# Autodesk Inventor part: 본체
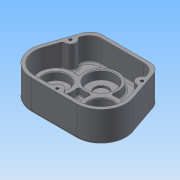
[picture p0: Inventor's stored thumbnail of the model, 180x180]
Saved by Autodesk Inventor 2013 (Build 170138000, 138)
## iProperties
Created: 2014-12
Part Number: 본체
Material: 일반
Document SubType Name: Modeling
Designer: Administrator
Density: 1 g/cm^3
Author: Administrator
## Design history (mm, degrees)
sketch "스케치1"
  geometry: L1 (0, 0)-(-32.527, -32.527); L2 (0, 0)-(32.527, -32.527); L3 (0, 0)-(0, -46); L4 (-47, 36)-(47, 36); L5 (-32.527, -68.527)-(32.527, -68.527); L6 (47, 36)-(66.565, -20.803); L7 (-47, 36)-(-66.565, -20.803); A1 r 46 centre (0, 0) between (-32.527, -32.527) and (32.527, -32.527); A2 r 36 centre (32.527, -32.527) between (32.527, -68.527) and (66.565, -20.803); A3 r 36 centre (-32.527, -32.527) between (-66.565, -20.803) and (-32.527, -68.527); 2 further points
  constraints: 14 end point, 7 point on circle, 3 centre point, 3 coincident, 3 tangent, 1 midpoint, 1 parallel, 1 perpendicular, 1 vertical, 1 vertical alignment
  dimensions: "d2" = 92 diameter of A1; "d3" = 90 deg angle of L2 L1; "d5" = 45 deg angle of L3 L1; "d9" = 94 distance of L4.start L4.end; "d10" = 36 distance from line of L4 point (0, 0)
extrude "돌출1" new body sketch "스케치1" distance "d11" = 44; taper "d12" = 0 deg
fillet "모깎기1" dims "d13" = 18
fillet "모깎기3" dims "d15" = 3
sketch "스케치27"
  geometry: L1 (-66.565, -20.803)-(-51.181, 23.862) reference; L2 (51.181, 23.862)-(66.565, -20.803) reference; L3 (-34.162, 36)-(34.162, 36) reference; L4 (-43.434, 31)-(-61.837, -22.432); L5 (43.434, 31)-(61.837, -22.432); L6 (-32.527, -63.527)-(32.527, -63.527); L7 (-43.434, 31)-(43.434, 31); L8 (-34.162, 36)-(34.162, 36) reference; L9 (51.181, 23.862)-(66.565, -20.803) reference; L10 (32.527, -68.527)-(-32.527, -68.527) reference; L11 (-66.565, -20.803)-(-51.181, 23.862) reference; A1 r 36 centre (-32.527, -32.527) between (-66.565, -20.803) and (-32.527, -68.527) reference; A2 r 36 centre (32.527, -32.527) between (32.527, -68.527) and (66.565, -20.803) reference; A3 r 31 centre (32.527, -32.527) between (32.527, -63.527) and (61.837, -22.432); A4 r 31 centre (-32.527, -32.527) between (-61.837, -22.432) and (-32.527, -63.527); A5 r 18 centre (-34.162, 18) between (-34.162, 36) and (-51.181, 23.862) reference; A6 r 18 centre (34.162, 18) between (51.181, 23.862) and (34.162, 36) reference; A7 r 36 centre (32.527, -32.527) between (32.527, -68.527) and (66.565, -20.803) reference; A8 r 36 centre (-32.527, -32.527) between (-66.565, -20.803) and (-32.527, -68.527) reference; 3 further points
  constraints: 8 end point, 4 point on circle, 4 tangent, 3 coincident, 2 centre point, 2 parallel, 1 midpoint, 1 vertical alignment
  dimensions: "d88" = 62 diameter of A3; "d90" = 62 diameter of A4; "d93" = 5 distance from line of L1 L4.start; "d94" = 5 distance from line of L3 point (0, 31); "d95" = 43.43386 distance of L5.start point (0, 31)
extrude "돌출17" cut sketch "스케치27" distance "d96" = 34; taper "d97" = 0 deg
fillet "모깎기5" dims "d98" = 18
sketch "스케치35"
  geometry: L1 (-61.837, -22.432)-(-47.615, 18.862) reference; L2 (-34.162, 36)-(34.162, 36) reference; A1 r 8 centre (-51.7, 7) between (-54.305, -0.564) and (-49.095, 14.564); 1 further point
  constraints: 3 point on line, 2 point on circle, 1 centre point
  dimensions: "d114" = 16 diameter of A1; "d115" = 29 distance from line of L2 A1.centre
extrude "돌출23" join sketch "스케치35" stored distance "d116" = 3; taper "d117" = 0 deg
sketch "스케치36"
  geometry: L1 (32.527, -63.527)-(-32.527, -63.527) reference; A1 r 8 centre (0, -63.527) between (8, -63.527) and (-8, -63.527); 1 further point
  constraints: 2 point on circle, 2 point on line, 1 centre point, 1 midpoint
  dimensions: "d118" = 16 diameter of A1
extrude "돌출24" join sketch "스케치36" stored distance "d119" = 3; taper "d120" = 0 deg
hole "구멍3" diameter "d123" = 4.134; stored, may be unused: countersink angle "d127" = 90 deg, drill point angle "d129" = 118 deg; dims "d121" = 10, "d122" = 10, "d124" = 20, "d125" = 4, "d126" = 2, "d128" = 23
hole "구멍4" diameter "d132" = 4.134; stored, may be unused: countersink angle "d136" = 90 deg, drill point angle "d138" = 118 deg; dims "d130" = 10, "d131" = 10, "d133" = 20, "d134" = 4, "d135" = 2, "d137" = 23
sketch "스케치37"
  geometry: C1 r 20 at (-32.527, -32.527); A1 r 33 centre (-32.527, -32.527) between (-63.728, -21.78) and (-32.527, -65.527) reference; 1 further point
  constraints: 1 centre point, 1 coincident
  dimensions: "d139" = 40 diameter of C1
extrude "돌출25" join sketch "스케치37" distance "d140" = 7; taper "d141" = -10 deg
sketch "스케치38"
  geometry: C1 r 18.766 at (0, 0) reference; C2 r 15 at (0, 0); 1 further point
  constraints: 1 centre point, 1 coincident
  dimensions: "d142" = 30 diameter of C2
extrude "돌출26" cut sketch "스케치38" distance "d143" = 7; taper "d144" = 0 deg
sketch "스케치39"
  geometry: C1 r 15 at (0, 0) reference; C2 r 7.75 at (0, 0); 1 further point
  constraints: 1 centre point, 1 coincident
  dimensions: "d145" = 15.5 diameter of C2
extrude "돌출27" cut sketch "스케치39" distance "d146" = 10; taper "d147" = 0 deg
sketch "스케치40"
  geometry: C1 r 7.75 at (32.527, -32.527) reference; C2 r 24 at (32.527, -32.527); A1 r 31 centre (32.527, -32.527) between (32.527, -63.527) and (61.837, -22.432) reference; 1 further point
  constraints: 1 centre point, 1 coincident
  dimensions: "d148" = 48 diameter of C2
extrude "돌출28" join sketch "스케치40" distance "d149" = 11; taper "d150" = 0 deg
sketch "스케치41"
  geometry: C1 r 7.75 at (0, 0) reference; C2 r 24 at (0, 0) reference; C3 r 17.5 at (0, 0); 1 further point
  constraints: 1 centre point, 1 coincident
  dimensions: "d151" = 35 diameter of C3
extrude "돌출29" cut sketch "스케치41" distance "d152" = 11; taper "d153" = 0 deg
sketch "스케치42"
  geometry: C1 r 24 at (0, 0); 1 further point
  constraints: 1 centre point, 1 coincident
  dimensions: "d154" = 48 diameter of C1
extrude "돌출30" join sketch "스케치42" distance "d155" = 11; taper "d156" = 0 deg
sketch "스케치43"
  geometry: C1 r 20 at (0, 0); A1 r 24 centre (0, 0) between (21.111, -11.416) and (11.416, -21.111) reference
  constraints: 1 centre point, 1 coincident
  dimensions: "d157" = 40 diameter of C1
extrude "돌출31" cut sketch "스케치43" distance "d158" = 12; taper "d159" = 0 deg
sketch "스케치44"
  geometry: C1 r 20 at (0, 0) reference; C2 r 10 at (0, 0)
  constraints: 1 centre point, 1 coincident
  dimensions: "d160" = 20 diameter of C2
extrude "돌출32" cut sketch "스케치44" distance "d161" = 3; taper "d162" = 0 deg
sketch "스케치45"
  geometry: C1 r 24 at (-32.527, -32.527); A1 r 31 centre (-32.527, -32.527) between (-61.837, -22.432) and (-32.527, -63.527) reference
  constraints: 1 centre point, 1 coincident
  dimensions: "d163" = 48 diameter of C1
extrude "돌출33" join sketch "스케치45" distance "d164" = 11; taper "d165" = 0 deg
sketch "스케치46"
  geometry: C1 r 17.5 at (-32.527, -32.527); A1 r 24 centre (-32.527, -32.527) between (-21.111, -11.416) and (-11.416, -21.111) reference
  constraints: 1 centre point, 1 coincident
  dimensions: "d166" = 35 diameter of C1
extrude "돌출34" cut sketch "스케치46" distance "d167" = 11; taper "d168" = 0 deg
sketch "스케치47"
  geometry: C1 r 20 at (32.527, -32.527); A1 r 33 centre (32.527, -32.527) between (32.527, -65.527) and (63.728, -21.78) reference; 1 further point
  constraints: 1 centre point, 1 coincident
  dimensions: "d169" = 40 diameter of C1
extrude "돌출35" join sketch "스케치47" distance "d170" = 7; taper "d171" = -10 deg
sketch "스케치48"
  geometry: C1 r 18.766 at (0, 0) reference; C2 r 15 at (0, 0); 1 further point
  constraints: 1 centre point, 1 coincident
  dimensions: "d172" = 30 diameter of C2
extrude "돌출36" cut sketch "스케치48" distance "d173" = 7; taper "d174" = 0 deg
sketch "스케치49"
  geometry: C1 r 15 at (0, 0) reference; C2 r 7.75 at (0, 0); 1 further point
  constraints: 1 centre point, 1 coincident
  dimensions: "d175" = 15.5 diameter of C2
extrude "돌출37" cut sketch "스케치49" stored distance "d176" = 10; taper "d177" = 0 deg
fillet "모깎기6" dims "d178" = 3
fillet "모깎기7" dims "d179" = 3
fillet "모깎기8" dims "d180" = 3
fillet "모깎기9" dims "d181" = 3
fillet "모깎기10" dims "d182" = 3
chamfer "모따기1" distance "d183" = 1; stored, may be unused: second distance "d184" = 2, angle "d185" = 45 deg
fillet "모깎기11" dims "d186" = 0.3
fillet "모깎기12" dims "d187" = 0.1
chamfer "모따기2" distance "d188" = 1; stored, may be unused: second distance "d189" = 2, angle "d190" = 45 deg
sketch "스케치50"
  geometry: L1 (34.162, 36)-(-34.162, 36) reference; 2 further points
  constraints: 1 vertical alignment, 1 other
  dimensions: "d191" = 30 distance from line of L1 point (0, 6)
feature "엠보싱1" sketch "스케치50" dims "d2" = 92, "d192" = 1, "d193" = 0
node "솔리드1"
mirror "대칭3"
node "절단 모서리 투영5"
other parameters: "d7" = 72, "d8" = 72
